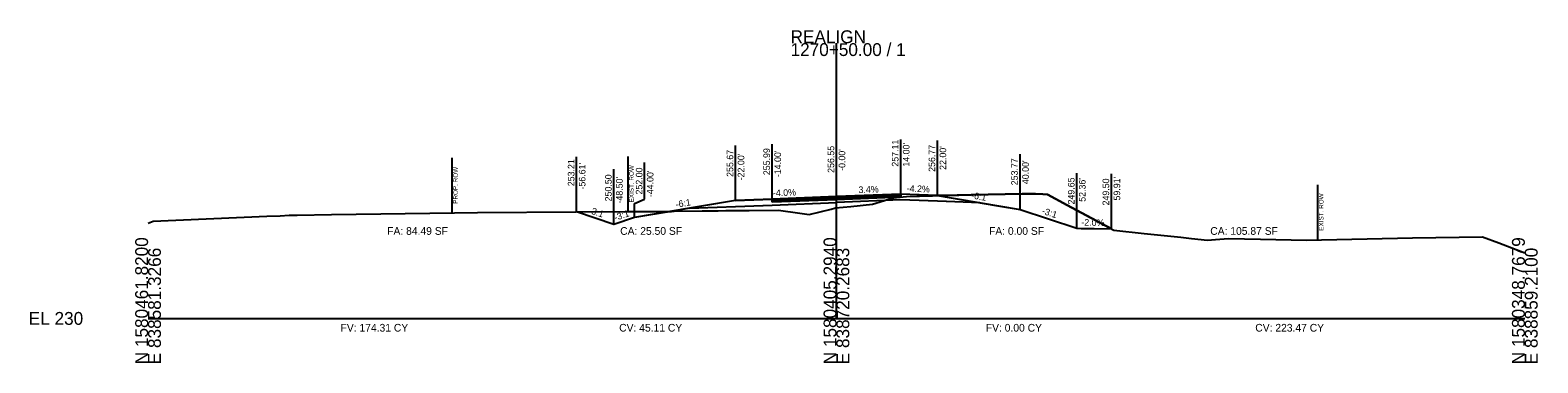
# Model space of a CAD drawing. Extents: x -26 to 6303, y -16 to 9563.
# Drawn here: x 4974.3 to 5302.8, y 3990.3 to 4062.8 of the extents above; entities that cross this region are included whole.
import ezdxf

# ---------------------------------------------------------------- set-up
doc = ezdxf.new("R2010")
doc.units = 0
for name, color, linetype in [('ASPHALT_19MM1', 7, 'Continuous'), ('ASPHALT_9_5MM1', 7, 'Continuous'), ('CONST_DCH', 7, 'Continuous'), ('CONST_LV3', 7, 'Continuous'), ('Default', 7, 'Continuous'), ('Draft_XS_Grid', 7, 'Continuous'), ('DTM_TEMP_DROP', 7, 'Continuous'), ('DTM_X_GROUND', 7, 'Continuous'), ('X_TRANS_EOP', 7, 'Continuous'), ('XS_CELL', 7, 'Continuous'), ('XS_M_SHAPES_EARTHWORK', 7, 'Continuous'), ('XS_P_ASPHALT', 7, 'Continuous'), ('XS_P_GROUND', 7, 'Continuous'), ('XS_P_ROW', 7, 'Continuous'), ('XS_P_SHOULDER', 7, 'Continuous'), ('XS_P_SUBGRADE_GRANULAR', 7, 'Continuous'), ('XS_P_TX_CLEARZONE', 7, 'Continuous'), ('XS_P_TX_FS_BS', 7, 'Continuous'), ('XS_SHEET_EW_TX_AREA', 7, 'Continuous'), ('XS_SHEET_EW_TX_VOLUME', 7, 'Continuous'), ('XS_X_ROW', 7, 'Continuous')]:
    doc.layers.add(name, color=color, linetype=linetype)

msp = doc.modelspace()

# ---------------------------------------------------------------- linework, layer by layer
at = {"layer": 'ASPHALT_19MM1'}
msp.add_lwpolyline([(5136, 4025.65), (5136, 4025.38), (5150, 4025.94), (5150, 4025.94), (5164, 4026.5), (5164, 4026.5), (5164, 4026.77), (5164, 4026.77), (5164, 4026.77), (5150, 4026.21), (5150, 4026.21), (5136, 4025.65), (5136, 4025.65)], dxfattribs=at)
at = {"layer": 'ASPHALT_9_5MM1'}
msp.add_lwpolyline([(5136, 4025.99), (5136, 4025.86), (5150, 4026.42), (5150, 4026.42), (5164, 4026.98), (5164, 4026.98), (5164, 4027.11), (5164, 4027.11), (5164, 4027.11), (5150, 4026.55), (5150, 4026.55), (5136, 4025.99), (5136, 4025.99)], dxfattribs=at)
at = {"layer": 'CONST_LV3'}
for points in [[(5164, 4027.11), (5150, 4026.55), (5150, 4026.55)], [(5172, 4026.77), (5164, 4027.11), (5164, 4027.11)], [(5117.97, 4024), (5106, 4022)]]:
    msp.add_lwpolyline(points, dxfattribs=at)
at = {"layer": 'Default'}
msp.add_lwpolyline([(5136, 4025.86), (5136, 4025.65), (5150, 4026.21), (5150, 4026.21), (5164, 4026.77), (5164, 4026.77), (5164, 4026.98), (5164, 4026.98), (5164, 4026.98), (5150, 4026.42), (5150, 4026.42), (5136, 4025.86), (5136, 4025.86)], dxfattribs=at)
at = {"layer": 'DTM_X_GROUND'}
msp.add_lwpolyline([(5000, 4020.78), (5001.12, 4021.23), (5025.9, 4022.27), (5028.75, 4022.39), (5030.73, 4022.47), (5032.47, 4022.54), (5039.98, 4022.64), (5066.74, 4022.99), (5071.76, 4023.06), (5114.65, 4023.35), (5120.77, 4023.43), (5124.23, 4023.47), (5125.92, 4023.49), (5131.01, 4023.55), (5137.36, 4023.62), (5142, 4022.96), (5144.03, 4022.66), (5148.85, 4023.84), (5149.79, 4024.07), (5153.13, 4024.42), (5157.84, 4024.92), (5161.45, 4026), (5162.43, 4026.3), (5163.06, 4026.36), (5165.27, 4026.61), (5176.7, 4026.89), (5179.38, 4026.95), (5190.46, 4027.14), (5193.37, 4027.18), (5194.98, 4027.07), (5195.97, 4027), (5200.31, 4024.66), (5210.45, 4019.21), (5217.08, 4018.53), (5225.08, 4017.68), (5227.34, 4017.44), (5230.87, 4017.05), (5232.61, 4017.17), (5235.46, 4017.42), (5242.4, 4017.27), (5252.43, 4017.06), (5275.54, 4017.57), (5290.76, 4017.81), (5294.35, 4016.45), (5300, 4014.3)], dxfattribs=at)
at = {"layer": 'XS_CELL'}
for p, q in [((5150, 4000), (5150, 4060)), ((5000, 4000), (5150, 4000)), ((5150, 4000), (5300, 4000))]:
    msp.add_line(p, q, dxfattribs=at)
at = {"layer": 'XS_M_SHAPES_EARTHWORK'}
for points in [[(5114.06, 4023.34), (5114.65, 4023.35), (5120.77, 4023.43), (5124.23, 4023.47), (5125.92, 4023.49), (5131.01, 4023.55), (5137.36, 4023.62), (5142, 4022.96), (5144.03, 4022.66), (5148.85, 4023.84), (5149.79, 4024.07), (5153.13, 4024.42), (5157.84, 4024.92), (5161.45, 4026), (5162.43, 4026.3), (5163.06, 4026.36), (5165.27, 4026.61), (5171.99, 4026.77), (5164, 4027.11), (5164, 4026.98), (5164, 4026.77), (5164, 4026.5), (5150, 4025.94), (5136, 4025.38), (5136, 4025.65), (5136, 4025.86), (5136, 4025.99), (5128, 4025.67), (5117.97, 4024)], [(5093.39, 4023.21), (5114.06, 4023.34), (5106, 4022), (5101.5, 4020.5)]]:
    msp.add_lwpolyline(points, close=True, dxfattribs=at)
at = {"layer": 'XS_P_GROUND'}
for points in [[(5128, 4025.67), (5106, 4022), (5101.5, 4020.5)], [(5172, 4026.77), (5190, 4023.77), (5202.36, 4019.65)], [(5101.5, 4020.5), (5093.39, 4023.21)], [(5202.36, 4019.65), (5203.36, 4019.63)], [(5203.36, 4019.63), (5209.91, 4019.5)]]:
    msp.add_lwpolyline(points, dxfattribs=at)
at = {"layer": 'XS_P_ROW'}
msp.add_line((5066.28, 4022.99), (5066.28, 4034.99), dxfattribs=at)
at = {"layer": 'XS_P_SHOULDER'}
for points in [[(5128, 4025.67), (5136, 4025.99), (5136, 4025.99)], [(5172, 4026.77), (5164, 4027.11), (5164, 4027.11)]]:
    msp.add_lwpolyline(points, dxfattribs=at)
at = {"layer": 'XS_P_SUBGRADE_GRANULAR'}
for points in [[(5117.97, 4024), (5134, 4024.64), (5134, 4024.64), (5136, 4024.72), (5136, 4024.72)], [(5136, 4024.72), (5150, 4025.28), (5150, 4025.28)], [(5164, 4025.84), (5164, 4025.84), (5150, 4025.28)], [(5181.24, 4025.23), (5174, 4025.52), (5174, 4025.52), (5164, 4025.84), (5164, 4025.84)]]:
    msp.add_lwpolyline(points, dxfattribs=at)
at = {"layer": 'XS_P_TX_CLEARZONE'}
for p, q in [((5128, 4025.67), (5128, 4037.67)), ((5136, 4025.99), (5136, 4037.99)), ((5150, 4026.55), (5150, 4038.55)), ((5164, 4027.03), (5164, 4039.03)), ((5172, 4026.77), (5172, 4038.77)), ((5093.39, 4023.21), (5093.39, 4035.21)), ((5190, 4023.77), (5190, 4035.77)), ((5101.5, 4020.5), (5101.5, 4032.5)), ((5108.21, 4026), (5108.21, 4034)), ((5202.36, 4019.65), (5202.36, 4031.65)), ((5209.91, 4019.5), (5209.91, 4031.5)), ((5106, 4025.06), (5108.21, 4026)), ((5106, 4022), (5106, 4025.06))]:
    msp.add_line(p, q, dxfattribs=at)
at = {"layer": 'XS_P_TX_FS_BS'}
for p, q in [((5176.7, 4026.89), (5172, 4026.77)), ((5190, 4023.77), (5202.36, 4019.65)), ((5202.36, 4019.65), (5209.91, 4019.5))]:
    msp.add_line(p, q, dxfattribs=at)
for points in [[(5172, 4026.77), (5185.15, 4024.57), (5190, 4023.77)], [(5209.91, 4019.5), (5200.31, 4024.66), (5195.97, 4027), (5194.98, 4027.07), (5193.37, 4027.18), (5190.46, 4027.14), (5179.38, 4026.95), (5176.33, 4026.84), (5176.7, 4026.89)]]:
    msp.add_lwpolyline(points, dxfattribs=at)
at = {"layer": 'XS_X_ROW'}
for p, q in [((5104.61, 4023.28), (5104.61, 4035.28)), ((5254.93, 4017.12), (5254.93, 4029.12))]:
    msp.add_line(p, q, dxfattribs=at)

# ---------------------------------------------------------------- texts
at = {"layer": 'CONST_DCH'}
for p in [(5171.92, 4026.65), (5189.92, 4023.65)]:
    msp.add_text('X', height=0.24, dxfattribs=at).set_placement(p)
at = {"layer": 'Draft_XS_Grid'}
msp.add_text('-', height=0.0001, dxfattribs=at).set_placement((5000, 4000))
at = {"layer": 'DTM_TEMP_DROP'}
for p in [(5135.92, 4025.87), (5149.92, 4026.43), (5163.92, 4026.99)]:
    msp.add_text('X', height=0.24, dxfattribs=at).set_placement(p)
at = {"layer": 'X_TRANS_EOP'}
msp.add_text('X', height=0.24, dxfattribs=at).set_placement((5093.31, 4023.09))
at = {"layer": 'XS_CELL'}
for s, p in [('REALIGN', (5140, 4060)), ('1270+50.00 / 1', (5140, 4057.2)), ('EL 230', (4974, 3998.6))]:
    msp.add_text(s, height=2.8, dxfattribs=at).set_placement(p)
for s, p in [('N 1580461.8200', (5000, 3990)), ('E 838581.3266', (5002.8, 3990)), ('N 1580405.2940', (5150, 3990)), ('E 838720.2683', (5152.8, 3990)), ('N 1580348.7679', (5300, 3990)), ('E 838859.2100', (5302.8, 3990))]:
    msp.add_text(s, height=2.8, rotation=90, dxfattribs=at).set_placement(p)
at = {"layer": 'XS_P_ASPHALT'}
msp.add_text('X', height=0.24, dxfattribs=at).set_placement((5105.92, 4021.88))
at = {"layer": 'XS_P_GROUND'}
msp.add_text('X', height=0.24, dxfattribs=at).set_placement((5171.92, 4026.65))
at = {"layer": 'XS_P_ROW'}
msp.add_text('PROP. ROW', height=1, rotation=90, dxfattribs=at).set_placement((5067.48, 4024.99))
at = {"layer": 'XS_P_SHOULDER'}
for p in [(5127.92, 4025.55), (5171.92, 4026.65), (5202.28, 4019.53)]:
    msp.add_text('X', height=0.24, dxfattribs=at).set_placement(p)
at = {"layer": 'XS_P_SUBGRADE_GRANULAR'}
for p in [(5101.43, 4020.38), (5209.83, 4019.38)]:
    msp.add_text('X', height=0.24, dxfattribs=at).set_placement(p)
at = {"layer": 'XS_P_TX_CLEARZONE'}
for s, p in [('257.11', (5163.52, 4033.08)), ("14.00'", (5165.92, 4033.08)), ('256.77', (5171.52, 4031.95)), ('253.21', (5092.91, 4028.81)), ('255.67', (5127.52, 4030.85)), ("-22.00'", (5129.92, 4030.1)), ('255.99', (5135.52, 4031.22)), ("-14.00'", (5137.92, 4030.78)), ('256.55', (5149.52, 4031.73)), ("-0.00'", (5151.92, 4032.16)), ("22.00'", (5173.92, 4032.38)), ('253.77', (5189.52, 4029.02)), ("-56.61'", (5095.31, 4028.09)), ('250.50', (5101.02, 4025.51)), ('252.00', (5107.73, 4027.01)), ("-44.00'", (5110.13, 4026.43)), ("40.00'", (5191.92, 4029.27)), ("-48.50'", (5103.42, 4025.04)), ('249.65', (5201.88, 4024.83)), ("52.36'", (5204.28, 4025.42)), ('249.50', (5209.43, 4024.62)), ("59.91'", (5211.83, 4025.7))]:
    msp.add_text(s, height=1.44, rotation=90, dxfattribs=at).set_placement(p)
at = {"layer": 'XS_P_TX_FS_BS'}
for s, rotation, p in [('-4.0%', 2.2906, (5136.18, 4026.6)), ('3.4%', 1.9645, (5154.83, 4027.31)), ('-4.2%', 357.6018, (5165.29, 4027.65)), ('-6:1', 9.4642, (5115.08, 4024.12)), ('-6:1', 350.5377, (5179.28, 4026.17)), ('3:1', 341.5651, (5096.47, 4022.81)), ('-3:1', 18.4332, (5101.84, 4021.25)), ('-3:1', 341.5651, (5194.65, 4022.86)), ('-2.0%', 358.8542, (5203.35, 4020.23))]:
    msp.add_text(s, height=1.44, rotation=rotation, dxfattribs=at).set_placement(p)
at = {"layer": 'XS_SHEET_EW_TX_AREA'}
for s, p in [('FA: 84.49 SF', (5052.11, 4018.22)), ('CA: 25.50 SF', (5102.88, 4018.22)), ('FA: 0.00 SF', (5183.25, 4018.22)), ('CA: 105.87 SF', (5231.46, 4018.22))]:
    msp.add_text(s, height=1.68, dxfattribs=at).set_placement(p)
at = {"layer": 'XS_SHEET_EW_TX_VOLUME'}
for s, p in [('FV: 174.31 CY', (5041.95, 3997.12)), ('CV: 45.11 CY', (5102.66, 3997.12)), ('FV: 0.00 CY', (5182.55, 3997.12)), ('CV: 223.47 CY', (5241.27, 3997.12))]:
    msp.add_text(s, height=1.68, dxfattribs=at).set_placement(p)
at = {"layer": 'XS_X_ROW'}
for p in [(5105.81, 4025.28), (5256.13, 4019.12)]:
    msp.add_text('EXIST. ROW', height=1, rotation=90, dxfattribs=at).set_placement(p)

doc.saveas('drawing.dxf')
